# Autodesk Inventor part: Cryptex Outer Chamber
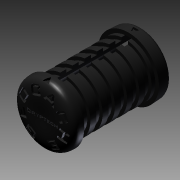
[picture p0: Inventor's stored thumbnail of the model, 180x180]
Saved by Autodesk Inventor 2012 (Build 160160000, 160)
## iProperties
Created: 2012-04
Part Number: Cryptex Outer Chamber
Material: ABS Plastic
Document SubType Name: Modeling
Designer: Pierce
Density: 1.06 g/cm^3
Mass: 112.472 g
Surface Area: 439.981 cm^2
Volume: 106.105 cm^3
Author: Pierce
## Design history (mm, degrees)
sketch "Sketch1"
  geometry: C1 r 24.765 at (0, 0); C2 r 21.59 at (0, 0); 1 further point
  constraints: 2 centre point, 1 coincident
  dimensions: "d0" = 49.53 diameter of C1; "d1" = 3.175 radial gap between concentric circles of C1 C2
extrude "Extrusion1" new body sketch "Sketch1" distance "d2" = 127; taper "d3" = 0 deg
sketch "Sketch2"
  geometry: L1 (-3.302, 24.765)-(3.302, 24.765); L2 (3.302, 24.765)-(3.302, 16.993); L3 (3.302, 16.993)-(-3.302, 16.993); L4 (-3.302, 16.993)-(-3.302, 24.765); L5 (0, 21.59)-(0, 24.765); 2 further points
  constraints: 10 end point, 3 parallel, 2 vertical alignment, 1 horizontal, 1 midpoint, 1 perpendicular, 3 other
  dimensions: "d4" = 6.604 distance of L1.start L1.end
extrude "Extrusion2" cut sketch "Sketch2" distance "d5" = 127; taper "d6" = 0 deg
sketch "Sketch3"
  geometry: C1 r 31.75 at (0, 0); A1 r 21.59 centre (0, 0) between (-3.302, 21.336) and (3.302, 21.336) reference
  constraints: 1 centre point, 1 coincident
  dimensions: "d7" = 63.5 diameter of C1
sketch "Sketch4"
  geometry: L1 (-24.765, 127)-(24.544, 127) reference; L2 (0, 127)-(0, 138.43); L3 (31.75, 127)-(-31.75, 127) reference; 2 further points
  constraints: 2 end point, 1 coincident, 1 perpendicular, 1 point on line
  dimensions: "d8" = 11.43 distance of L2.start L2.end
workplane "Work Plane5"
sketch "Sketch5"
  geometry: L1 (-3.343, 21.355)-(3.261, 21.355); L2 (3.261, 21.355)-(3.261, 29.841); L3 (3.261, 29.841)-(-3.343, 29.841); L4 (-3.343, 29.841)-(-3.343, 21.355); L5 (-3.343, 24.563)-(-3.343, 27.763); L6 (3.261, 27.763)-(3.261, 24.563); C1 r 24.765 at (-0.041, 0.019); A1 r 21.59 centre (-0.041, 0.019) between (-3.343, 21.355) and (3.261, 21.355); A2 r 24.765 centre (-0.041, 0.019) between (-3.343, 24.563) and (3.261, 24.563); A3 r 27.94 centre (-0.041, 0.019) between (-3.343, 27.763) and (3.261, 27.763); 1 further point
  constraints: 12 end point, 7 point on circle, 4 centre point, 3 parallel, 2 coincident, 2 point on line, 1 concentric, 1 horizontal, 1 perpendicular
  dimensions: "d14" = 55.88 diameter of A3 (computed from d0)
extrude "Extrusion3" join sketch "Sketch5" distance "d15" = 3.81; taper "d16" = 0 deg
workplane "Work Plane1"
sketch "Sketch6"
  geometry: L1 (-3.343, 27.763)-(-3.343, 24.563) reference; L2 (3.261, 24.563)-(3.261, 27.763) reference; L3 (-3.343, 24.563)-(-3.343, 27.763); L4 (3.261, 24.563)-(3.261, 27.763); A1 r 27.94 centre (-0.041, 0.019) between (-3.343, 27.763) and (3.261, 27.763) reference; A2 r 24.765 centre (-0.041, 0.019) between (-3.343, 24.563) and (3.261, 24.563) reference; A3 r 27.94 centre (-0.041, 0.019) between (-3.343, 27.763) and (3.261, 27.763); 2 further points
  constraints: 4 end point, 2 coincident, 2 parallel, 2 point on circle, 1 centre point, 1 concentric, 4 other
extrude "Extrusion4" join sketch "Sketch6" distance "d18" = 6.35; taper "d19" = 0 deg
pattern_linear "Rectangular Pattern1" dims "d22" = 12.7
workplane "Work Plane2"
sketch "Sketch7"
  geometry: L1 (-3.302, 27.744)-(-3.302, 24.544) reference; L2 (3.302, 24.544)-(3.302, 27.744) reference; L3 (-3.302, 27.744)-(-3.302, 24.544); L4 (3.302, 24.544)-(3.302, 27.94); A1 r 24.765 centre (0, 0) between (-3.302, 24.544) and (3.302, 24.544) reference; A2 r 27.94 centre (0, 0) between (-3.302, 27.744) and (3.302, 27.744) reference; A3 r 27.94 centre (0, 0) between (-3.302, 27.744) and (3.302, 27.744); A4 r 24.765 centre (0, 0) between (-3.302, 24.544) and (3.302, 24.544); 1 further point
  constraints: 4 end point, 4 point on circle, 2 centre point, 2 coincident, 2 concentric, 2 parallel, 1 point on line
extrude "Extrusion5" join sketch "Sketch7" distance "d24" = 3.81; taper "d25" = 0 deg
workplane "Work Plane3"
sketch "Sketch8"
  geometry: L1 (3.302, 24.544)-(3.302, 27.744) reference; L2 (-3.302, 27.744)-(-3.302, 24.544) reference; L3 (-53.179, 36.058)-(83.459, 36.058); L4 (83.459, 36.058)-(83.459, -50.716); L5 (83.459, -50.716)-(-53.179, -50.716); L6 (-53.179, -50.716)-(-53.179, 36.058); A1 r 24.765 centre (0, 0) between (-3.302, 24.544) and (3.302, 24.544) reference; A2 r 27.94 centre (0, 0) between (-3.302, 27.744) and (3.302, 27.744) reference
  constraints: 8 end point, 2 parallel, 1 horizontal, 1 perpendicular
extrude "Extrusion6" cut sketch "Sketch8" distance "d27" = 50.8; taper "d28" = 0 deg
sketch "Sketch9"
  geometry: C1 r 31.75 at (0, 0); C2 r 31.75 at (0, 0); A1 r 27.94 centre (0, 0) between (-3.302, 27.744) and (3.302, 27.744) reference
  constraints: 2 centre point, 2 coincident, 1 concentric
  dimensions: "d29" = 63.5 diameter of C1
sketch "Sketch10"
  geometry: L1 (27.744, 49.53)-(-27.94, 49.53) reference; L2 (-0.098, 49.53)-(-0.098, 43.18); 2 further points
  constraints: 2 end point, 1 coincident, 1 midpoint, 1 perpendicular
  dimensions: "d30" = 6.35 distance of L2.start L2.end
sketch "Sketch12"
  geometry: L1 (0, 127)-(0, 138.43) reference; L2 (0, 127)-(0, 132.715); 1 further point
  constraints: 2 end point, 1 midpoint
workplane "Work Plane13"
workplane "Work Plane4"
sketch "Sketch13"
  geometry: C1 r 31.115 at (0, 0); 1 further point
  constraints: 1 centre point, 1 coincident
  dimensions: "d41" = 62.23 diameter of C1
loft "Loft3" sketch "Sketch13" dims "d42" = 10, "d43" = 90 deg, "d44" = 0, "d45" = 90 deg, "d86" = 10, "d87" = 90 deg
workplane "Work Plane6"
workplane "Work Plane7"
workplane "Work Plane9"
sketch "Sketch17"
  geometry: L1 (0, 49.53)-(0, 43.18) reference; L2 (-21.59, 49.53)-(21.59, 49.53) reference; L3 (0, 49.53)-(0, 36.83); 4 further points
  constraints: 2 end point, 1 coincident, 1 perpendicular
  dimensions: "d62" = 12.7 distance of L1.start L3.end
workplane "Work Plane10"
sketch "Sketch16"
  geometry: C1 r 31.115 at (0, 0); 1 further point
  constraints: 1 centre point, 1 coincident
  dimensions: "d61" = 62.23 diameter of C1
sketch "Sketch18"
  geometry: 1 further point
workplane "Work Plane11"
loft "Loft5" dims "d69" = 0, "d70" = 90 deg, "d71" = 0, "d72" = 90 deg
fillet "Fillet4" dims "d73" = 3.175
sketch "Sketch15"
  geometry: L1 (-3.343, 27.763)-(-3.343, 21.355) reference; L2 (-3.343, 27.763)-(-3.343, 24.563) reference; L3 (-3.343, 24.563)-(-3.343, 27.763) reference; L4 (-3.343, 27.763)-(-3.343, 24.563) reference; L5 (-3.343, 24.563)-(-3.343, 27.763) reference; L6 (-3.343, 27.763)-(-3.343, 24.563) reference; L7 (-3.343, 24.563)-(-3.343, 27.763) reference; L8 (-3.343, 27.763)-(-3.343, 24.563) reference; L9 (-3.343, 24.563)-(-3.343, 27.763) reference; L10 (-3.343, 27.763)-(-3.343, 24.563) reference; L11 (-3.343, 24.563)-(-3.343, 27.763) reference; L12 (-3.343, 27.763)-(-3.343, 24.563) reference; L13 (-3.343, 24.563)-(-3.343, 27.763) reference; L14 (-3.343, 27.763)-(-3.343, 24.563) reference; L15 (3.261, 24.563)-(3.261, 27.763) reference; L16 (-3.343, 24.563)-(-3.343, 27.763); L17 (-3.343, 27.763)-(3.261, 27.763); L18 (3.261, 27.763)-(3.261, 24.563); L19 (-3.343, 21.355)-(-3.343, 24.563); L20 (3.261, 24.563)-(3.261, 21.355); L21 (-3.343, 27.763)-(-3.343, 21.355) reference; A1 r 24.765 centre (-0.041, 0.019) between (-3.343, 24.563) and (3.261, 24.563) reference; A2 r 24.765 centre (-0.041, 0.019) between (-3.343, 24.563) and (3.261, 24.563) reference; A3 r 24.765 centre (-0.041, 0.019) between (-3.343, 24.563) and (3.261, 24.563) reference; A4 r 27.94 centre (-0.041, 0.019) between (-3.343, 27.763) and (3.261, 27.763) reference; A5 r 24.765 centre (-0.041, 0.019) between (-3.343, 24.563) and (3.261, 24.563); A6 r 21.59 centre (-0.041, 0.019) between (-3.343, 21.355) and (3.261, 21.355) reference; A7 r 21.59 centre (-0.041, 0.019) between (-3.343, 21.355) and (3.261, 21.355); A8 r 21.59 centre (-0.041, 0.019) between (-3.343, 21.355) and (3.261, 21.355) reference; 1 further point
  constraints: 10 end point, 4 point on circle, 3 parallel, 2 centre point, 2 coincident, 1 collinear, 1 perpendicular
extrude "Extrusion9" cut sketch "Sketch15" stored distance "d59" = 21.59; taper "d60" = 0 deg
sketch "Sketch14"
  geometry: L1 (1.588, 135.039)-(-1.587, 135.039); L2 (-1.587, 135.039)-(1.588, 135.039); L3 (-3.175, 135.039)-(3.175, 135.039); L4 (3.175, 135.039)-(0, 129.54); L5 (0, 129.54)-(-3.175, 135.039); L6 (3.175, 135.039)-(1.588, 135.039); L7 (-1.587, 135.039)-(-3.175, 135.039); L8 (-31.75, 127)-(31.75, 127) reference; L9 (3.302, 127)-(3.302, 123.19) reference; L10 (-3.302, 127)-(-3.302, 123.19) reference; L11 (27.94, 49.53)-(-27.94, 49.53) reference; L12 (0, 127)-(0, 49.53); L13 (0, 88.265)-(50.586, 88.265); L14 (3.175, 41.491)-(0, 46.99); L15 (0, 46.99)-(-3.175, 41.491); L16 (-3.175, 41.491)-(3.175, 41.491); 5 further points; 2 other entities
  constraints: 24 end point, 4 coincident, 4 symmetric about line, 3 collinear, 3 horizontal, 3 midpoint, 1 parallel, 1 perpendicular, 4 other
  dimensions: "d49" = 60 deg angle of L3 L5; "d50" = 60 deg angle of L4 L3; "d51" = 6.35 distance of L3.start L3.end; "d52" = 3.175 distance of L1.start L1.end; "d53" = 1.5875 dimension on L3.end; "d54" = 0 distance of L2.end L1.start; "d55" = 2.54 distance from line of L8 L4.end
extrude "Extrusion8" cut sketch "Sketch14" distance "d56" = 21.59; taper "d57" = 0 deg
workplane "Work Plane12"
sketch "Sketch19"
  geometry: L1 (0, 0)-(0, -24.765); L2 (4.583, -17.103)-(0, -17.103); L3 (-4.583, -17.103)-(0, -17.103); A1 r 24.765 centre (0, 0) between (-3.302, 24.544) and (3.302, 24.544) reference; A2 r 17.707 centre (0, 0) between (4.583, -17.103) and (-4.583, -17.103); 6 further points
  constraints: 6 end point, 3 point on circle, 2 perpendicular, 2 point on line, 1 centre point, 1 coincident, 1 collinear, 1 horizontal alignment, 4 other
  dimensions: "d75" = 30 deg dimension on L1.start L3.start L2.start
extrude "Extrusion10" cut sketch "Sketch19" distance "d76" = 41.91; taper "d77" = 0 deg
chamfer "Chamfer2" distance "d78" = 1.905; stored, may be unused: second distance "d79" = 3.175, angle "d80" = 45 deg
workplane "Work Plane15"
sketch "Sketch23"
  geometry: L1 (-6.17, 6.166)-(6.53, 6.166); L2 (6.53, 6.166)-(6.53, -6.534); L3 (6.53, -6.534)-(-6.17, -6.534); L4 (-6.17, -6.534)-(-6.17, 6.166); L5 (-6.17, -0.184)-(6.53, -0.184); L6 (0.18, -6.534)-(0.18, 6.166); 3 further points
  constraints: 4 end point, 4 midpoint, 1 horizontal alignment, 2 other
  dimensions: "d90" = 12.7 distance of L1.start L1.end; "d91" = 12.7 distance of L3.end L1.start
extrude "Extrusion12" cut sketch "Sketch23" distance "d92" = 25.4; taper "d93" = 0 deg
body "Solid1"
node "Projected Loop1"
node "Projected Loop2"
node "Projected Loop3"
node "Projected Loop4"
node "Projected Loop5"
node "Projected Loop6"
other parameters: "d23" = 6.35, "d26" = 6.35, "d48" = 50.8, "d58" = 76.2, "d74" = -50.8, "d89" = 22.225
